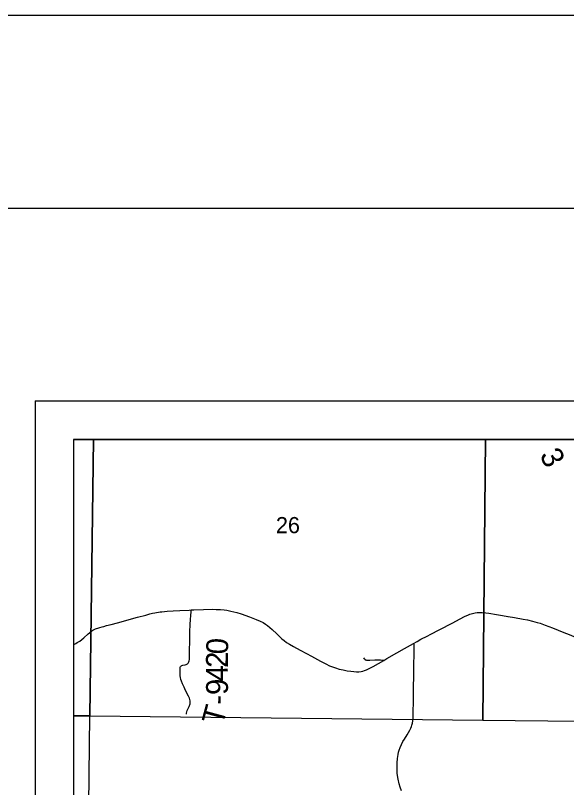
# Model space of a CAD drawing. Extents: x 0 to 34, y 0 to 22.
# Drawn here: x 1.949 to 3.378, y 19.997 to 22 of the extents above; entities that cross this region are included whole.
import ezdxf

# ---------------------------------------------------------------- set-up
doc = ezdxf.new("R2010")
doc.units = 0
for name, color, linetype in [('GM_X_Corporation', 7, 'Continuous'), ('GM_X_County_Road', 7, 'Continuous'), ('GM_X_Section_Text', 7, 'Continuous'), ('GM_X_State_Route', 7, 'Continuous'), ('GM_X_Township_Road', 7, 'Continuous'), ('GM_X_Township_Road_Text', 7, 'Continuous'), ('GM_X_Township_Text', 7, 'Continuous'), ('SH_Border', 7, 'Continuous'), ('SH_Cut_Line', 7, 'Continuous'), ('SH_Data', 7, 'Continuous')]:
    doc.layers.add(name, color=color, linetype=linetype)

msp = doc.modelspace()

# ---------------------------------------------------------------- linework, layer by layer
at = {"layer": 'GM_X_Corporation'}
for points in [[(2.1517, 20.9), (2.1, 20.9), (2.1, 20.1831), (2.142, 20.1827)], [(3.1678, 20.9), (2.1517, 20.9), (2.142, 20.1827), (3.1616, 20.1718)], [(4.1826, 20.9), (3.1678, 20.9), (3.1616, 20.1718), (4.1713, 20.1609)], [(2.1, 20.1831), (2.1, 19.1797), (2.1129, 19.1796), (2.1306, 19.1793), (2.142, 20.1827)]]:
    msp.add_lwpolyline(points, close=True, dxfattribs=at)
at = {"layer": 'GM_X_County_Road'}
msp.add_lwpolyline([(2.9499, 19.9886), (2.9469, 19.998), (2.9443, 20.0069), (2.9415, 20.019), (2.9398, 20.0281), (2.9391, 20.0342), (2.9388, 20.0403), (2.9389, 20.0509), (2.9392, 20.0614), (2.9401, 20.0719), (2.9414, 20.0823), (2.9426, 20.0889), (2.9441, 20.0942), (2.9465, 20.1006), (2.95, 20.1085), (2.9539, 20.1162), (2.9577, 20.1225), (2.965, 20.134), (2.972, 20.1458), (2.9746, 20.1508), (2.9764, 20.1549), (2.9775, 20.1585), (2.9788, 20.164), (2.9799, 20.1702), (2.9804, 20.1759), (2.9809, 20.1871), (2.9809, 20.2026), (2.9811, 20.2095), (2.9813, 20.2237), (2.9813, 20.2393), (2.9814, 20.2473), (2.9815, 20.2647), (2.9819, 20.2784), (2.9819, 20.2833), (2.9823, 20.3038), (2.9825, 20.3168), (2.9827, 20.3411), (2.9829, 20.3535), (2.983, 20.3591), (2.9831, 20.3642), (2.9831, 20.366), (2.9829, 20.3678), (2.9826, 20.3689), (2.9818, 20.37), (2.9812, 20.3707)], dxfattribs=at)
at = {"layer": 'GM_X_State_Route'}
for points in [[(2.1, 20.3684), (2.102, 20.3693), (2.1056, 20.371), (2.1093, 20.3729), (2.1129, 20.375), (2.1158, 20.3768), (2.1213, 20.3809), (2.1266, 20.3853), (2.1379, 20.396), (2.141, 20.3986), (2.1441, 20.4011), (2.1472, 20.4032), (2.1502, 20.405), (2.1534, 20.4066), (2.1568, 20.4083), (2.1597, 20.4095), (2.1632, 20.4108), (2.1679, 20.4122), (2.1737, 20.414), (2.1782, 20.4151), (2.1852, 20.4169), (2.1975, 20.42), (2.2139, 20.4246), (2.266, 20.4388), (2.287, 20.4445), (2.298, 20.4473), (2.3044, 20.4489), (2.3104, 20.4502), (2.3152, 20.451), (2.3202, 20.4518), (2.3242, 20.4524), (2.3287, 20.453), (2.3355, 20.4537), (2.3429, 20.4543), (2.3578, 20.4554), (2.3757, 20.4564), (2.3995, 20.4575), (2.4052, 20.4579), (2.4114, 20.4582), (2.4365, 20.4589), (2.4595, 20.4593), (2.47, 20.4592), (2.4812, 20.4587), (2.4904, 20.4579), (2.4977, 20.4568), (2.5081, 20.4548), (2.5159, 20.453), (2.523, 20.451), (2.5342, 20.4474), (2.5558, 20.4396), (2.5738, 20.4326), (2.5841, 20.4284), (2.5912, 20.4249), (2.5975, 20.421), (2.603, 20.4171), (2.6088, 20.4124), (2.6152, 20.4066), (2.6267, 20.3953), (2.6339, 20.3884), (2.6399, 20.383), (2.6457, 20.3783), (2.6523, 20.3735), (2.6602, 20.3685), (2.6699, 20.3629), (2.6879, 20.3531), (2.7037, 20.3445), (2.7168, 20.3374), (2.7403, 20.3246), (2.7541, 20.3175), (2.7637, 20.3129), (2.7712, 20.3098), (2.7789, 20.3071), (2.7885, 20.3044), (2.7988, 20.302), (2.8092, 20.3), (2.8191, 20.2984), (2.8265, 20.2976), (2.8334, 20.2973), (2.8397, 20.2974), (2.8453, 20.2981), (2.8503, 20.2991), (2.8545, 20.3004), (2.8592, 20.3022), (2.8649, 20.3049), (2.8764, 20.311), (2.9041, 20.3269), (2.9125, 20.3317), (2.9379, 20.3462), (2.9584, 20.3579), (2.9812, 20.3707), (2.9909, 20.3761), (3.0007, 20.3815), (3.0167, 20.3896), (3.0267, 20.3947), (3.048, 20.4062), (3.0833, 20.4245), (3.1009, 20.4337), (3.1158, 20.4414), (3.122, 20.4442), (3.1277, 20.4464), (3.1341, 20.4484), (3.1414, 20.4501), (3.1468, 20.451), (3.151, 20.4512), (3.1596, 20.4509), (3.1689, 20.4501), (3.1768, 20.449), (3.1968, 20.4458), (3.2119, 20.4433), (3.2257, 20.441)], [(3.2257, 20.441), (3.2267, 20.4408), (3.2432, 20.438), (3.2659, 20.4341), (3.2768, 20.4319), (3.2901, 20.4288), (3.302, 20.4255), (3.3097, 20.4231), (3.3225, 20.4185), (3.3416, 20.411), (3.3716, 20.3991), (3.3849, 20.394), (3.3975, 20.3888), (3.4094, 20.3838), (3.4109, 20.3833)]]:
    msp.add_lwpolyline(points, dxfattribs=at)
at = {"layer": 'GM_X_Township_Road'}
for points in [[(2.3928, 20.1877), (2.3929, 20.1895), (2.3934, 20.1932), (2.3944, 20.1968), (2.3958, 20.2001), (2.3994, 20.2071), (2.4005, 20.2094), (2.4012, 20.2111), (2.4021, 20.214), (2.4025, 20.217), (2.4025, 20.2182), (2.4021, 20.2219), (2.4013, 20.2249), (2.4001, 20.2285), (2.3976, 20.2342), (2.3905, 20.2487), (2.3864, 20.2571), (2.3825, 20.2656), (2.3798, 20.2725), (2.3783, 20.2773), (2.3772, 20.2821), (2.3766, 20.2864), (2.3762, 20.2938), (2.376, 20.3025), (2.3762, 20.3056), (2.3767, 20.3091), (2.3774, 20.3106), (2.3784, 20.3117), (2.3795, 20.3127), (2.3806, 20.3134), (2.3834, 20.3143), (2.3897, 20.3151), (2.3921, 20.3159), (2.3937, 20.3167), (2.3957, 20.3182), (2.3969, 20.3196), (2.398, 20.3211), (2.399, 20.3234), (2.3997, 20.3258), (2.4002, 20.3295), (2.4006, 20.3363), (2.4008, 20.3512), (2.4011, 20.3774), (2.4018, 20.4004), (2.4025, 20.4209), (2.4031, 20.432), (2.4041, 20.4444), (2.4047, 20.4523), (2.4052, 20.4579)], [(2.8518, 20.3335), (2.8535, 20.3309), (2.8548, 20.3296), (2.8563, 20.3285), (2.8575, 20.3281), (2.8593, 20.3277), (2.863, 20.3274), (2.8685, 20.3273), (2.8809, 20.3278), (2.8908, 20.3282), (2.8962, 20.3279), (2.8996, 20.3276), (2.9034, 20.327), (2.9041, 20.3269)]]:
    msp.add_lwpolyline(points, dxfattribs=at)
at = {"layer": 'GM_X_Township_Text'}
msp.add_lwpolyline([(7.231, 20.9), (2.1, 20.9), (2.1, 19.1775)], dxfattribs=at)
at = {"layer": 'SH_Border'}
msp.add_lwpolyline([(1.5, 21.5), (33.5, 21.5), (33.5, 0.5), (1.5, 0.5)], close=True, dxfattribs=at)
at = {"layer": 'SH_Cut_Line'}
msp.add_lwpolyline([(0, 0), (34, 0), (34, 22), (0, 22)], close=True, dxfattribs=at)
at = {"layer": 'SH_Data'}
for p, q in [((2, 21), (9, 21)), ((2, 21), (2, 14)), ((2.1, 20.9), (2.1, 14.1)), ((2.1, 20.9), (8.9, 20.9))]:
    msp.add_line(p, q, dxfattribs=at)

# ---------------------------------------------------------------- texts
at = {"layer": 'GM_X_Section_Text'}
msp.add_text('26', height=0.04186, rotation=0, dxfattribs=at).set_placement((2.6246, 20.6568))
at = {"layer": 'GM_X_Township_Road_Text'}
for s, rotation, p in [('3', 296.8694, (3.3073, 20.8596)), ('0', 88.1054, (2.5001, 20.3417)), ('2', 89.5889, (2.4999, 20.3071)), ('4', 90.5766, (2.5002, 20.2723)), ('9', 90.5299, (2.5005, 20.2373)), ('-', 87.994, (2.4997, 20.2112)), ('T', 74.8411, (2.4865, 20.1562))]:
    msp.add_text(s, height=0.0568, rotation=rotation, dxfattribs=at).set_placement(p)

doc.saveas('drawing.dxf')
